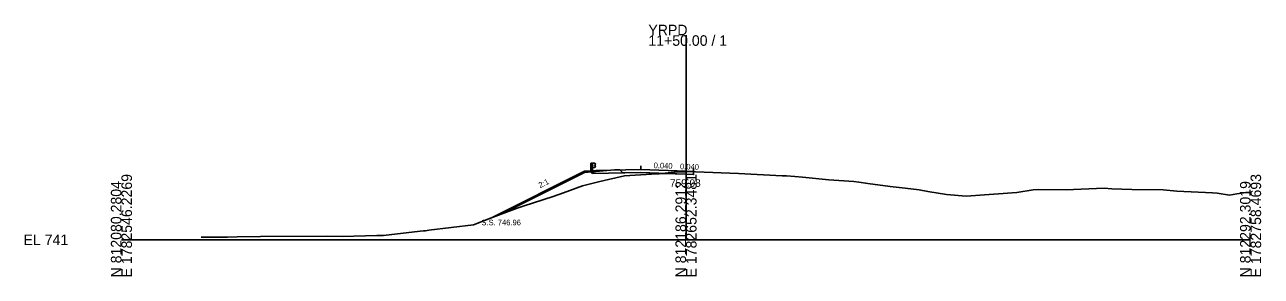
# Model space of a CAD drawing. Extents: x -26 to 1403, y -10 to 9544.
# Drawn here: x -25.7 to 302.8, y 1490.3 to 1557.2 of the extents above; entities that cross this region are included whole.
import ezdxf

# ---------------------------------------------------------------- set-up
doc = ezdxf.new("R2010")
doc.units = 0
for name, color, linetype in [('Exist Cross Section Cell', 7, 'Continuous'), ('Exist XS Center Line Elevation Label', 7, 'Continuous'), ('Exist XS Ground Line', 7, 'Continuous'), ('Prop XS Dump Level', 7, 'Continuous'), ('Prop XS Earthwork Shape', 7, 'Continuous'), ('Prop XS EOT Tick Mark', 7, 'Continuous'), ('Prop XS Finish Grade', 7, 'Continuous'), ('Prop XS Finish Grade Earthwork', 7, 'Continuous'), ('Prop XS Finish Grade Paved Shoulder', 7, 'Continuous'), ('Prop XS Finish Grade Pavement', 7, 'Continuous'), ('Prop XS Guardrail', 7, 'Continuous'), ('Prop XS Pvmt Edge Slope', 7, 'Continuous'), ('Prop XS SE Text', 7, 'Continuous'), ('Prop XS Side Slope Text', 7, 'Continuous'), ('Prop XS SS Elevation Text', 7, 'Continuous'), ('Prop XS Subgrade Earthwork', 7, 'Continuous')]:
    doc.layers.add(name, color=color, linetype=linetype)

msp = doc.modelspace()

# ---------------------------------------------------------------- linework, layer by layer
at = {"layer": 'Exist Cross Section Cell'}
for p, q in [((150, 1500), (150, 1554.35)), ((0, 1500), (150, 1500)), ((150, 1500), (300, 1500))]:
    msp.add_line(p, q, dxfattribs=at)
at = {"layer": 'Exist XS Ground Line'}
for p, q in [((142.9, 1517.49), (147.62, 1518.04)), ((147.62, 1518.04), (149.08, 1518.07)), ((149.08, 1518.07), (150, 1518.08)), ((150, 1518.08), (152.12, 1518.12)), ((152.12, 1518.12), (152.55, 1518.1)), ((152.55, 1518.1), (163.95, 1517.65)), ((122.46, 1514.34), (127.13, 1515.48)), ((127.13, 1515.48), (133.67, 1516.98)), ((133.67, 1516.98), (140.8, 1517.41)), ((140.8, 1517.41), (142.9, 1517.49)), ((163.95, 1517.65), (175.58, 1517.03)), ((175.58, 1517.03), (176.7, 1516.96)), ((176.7, 1516.96), (178.88, 1516.83)), ((178.88, 1516.83), (180.91, 1516.61)), ((180.91, 1516.61), (187.99, 1515.97)), ((187.99, 1515.97), (194.56, 1515.47)), ((194.56, 1515.47), (195.89, 1515.31)), ((195.89, 1515.31), (198.3, 1514.98)), ((198.3, 1514.98), (204.21, 1514.13)), ((109.48, 1509.8), (114.7, 1511.47)), ((114.7, 1511.47), (117.46, 1512.51)), ((117.46, 1512.51), (122.46, 1514.34)), ((204.21, 1514.13), (208.2, 1513.7)), ((208.2, 1513.7), (211.95, 1513.31)), ((211.95, 1513.31), (214.25, 1512.87)), ((214.25, 1512.87), (219.18, 1512.04)), ((219.18, 1512.04), (224.47, 1511.63)), ((224.47, 1511.63), (237.91, 1512.57)), ((237.91, 1512.57), (242.24, 1513.32)), ((242.24, 1513.32), (243.57, 1513.35)), ((243.57, 1513.35), (250.98, 1513.28)), ((250.98, 1513.28), (252.95, 1513.35)), ((252.95, 1513.35), (261.09, 1513.73)), ((261.09, 1513.73), (263.13, 1513.55)), ((263.13, 1513.55), (268.43, 1513.36)), ((268.43, 1513.36), (276.79, 1513.3)), ((276.79, 1513.3), (280.43, 1512.92)), ((280.43, 1512.92), (289.85, 1512.52)), ((289.85, 1512.52), (291.1, 1512.35)), ((291.1, 1512.35), (294.41, 1511.88)), ((294.41, 1511.88), (296.38, 1512.2)), ((296.38, 1512.2), (298.72, 1512.55)), ((298.72, 1512.55), (300, 1512.59)), ((98.04, 1505.79), (105.1, 1508.43)), ((105.1, 1508.43), (106.98, 1508.99)), ((106.98, 1508.99), (109.48, 1509.8)), ((93.58, 1503.96), (98.04, 1505.79)), ((69.59, 1501.18), (79.36, 1502.27)), ((79.36, 1502.27), (80.24, 1502.34)), ((80.24, 1502.34), (80.77, 1502.4)), ((80.77, 1502.4), (81.68, 1502.52)), ((81.68, 1502.52), (93.58, 1503.96)), ((21.2, 1500.67), (28.15, 1500.69)), ((28.15, 1500.69), (30.71, 1500.75)), ((30.71, 1500.75), (36.99, 1500.85)), ((36.99, 1500.85), (54.44, 1500.95)), ((54.44, 1500.95), (58.77, 1500.87)), ((58.77, 1500.87), (67.89, 1501.13)), ((67.89, 1501.13), (69.59, 1501.18))]:
    msp.add_line(p, q, dxfattribs=at)
at = {"layer": 'Prop XS Dump Level'}
for p, q in [((138, 1518.69), (150, 1518.21)), ((150, 1518.21), (152, 1518.13))]:
    msp.add_line(p, q, dxfattribs=at)
at = {"layer": 'Prop XS Earthwork Shape'}
for points in [[(123, 1517.91), (100.87, 1506.85), (105.1, 1508.43), (106.98, 1508.99), (109.48, 1509.8), (114.7, 1511.47), (117.46, 1512.51), (122.46, 1514.34), (127.13, 1515.48), (133.67, 1516.98), (140.8, 1517.41), (142.9, 1517.49), (144.27, 1517.65), (137.99, 1517.9), (133.19, 1517.8), (132.42, 1518.58), (131, 1518.55)], [(149.97, 1517.42), (152, 1517.34), (152, 1518.12), (150, 1518.08), (149.08, 1518.07), (147.62, 1518.04), (144.27, 1517.65)]]:
    msp.add_lwpolyline(points, close=True, dxfattribs=at)
at = {"layer": 'Prop XS EOT Tick Mark'}
for p, q in [((138, 1518.69), (138, 1519.69)), ((152, 1518.13), (152, 1519.13))]:
    msp.add_line(p, q, dxfattribs=at)
at = {"layer": 'Prop XS Finish Grade'}
msp.add_line((124.5, 1518.33), (126, 1518.45), dxfattribs=at)
at = {"layer": 'Prop XS Finish Grade Earthwork'}
for q in [(98.5, 1505.96), (124.5, 1518.33)]:
    msp.add_line((123, 1518.21), q, dxfattribs=at)
at = {"layer": 'Prop XS Finish Grade Paved Shoulder'}
msp.add_line((138, 1518.69), (126, 1518.45), dxfattribs=at)
at = {"layer": 'Prop XS Finish Grade Pavement'}
for p, q in [((138, 1518.69), (150, 1518.21)), ((150, 1518.21), (152, 1518.13))]:
    msp.add_line(p, q, dxfattribs=at)
at = {"layer": 'Prop XS Guardrail'}
for p, q in [((124.68, 1520.36), (125.18, 1520.36)), ((124.68, 1517.86), (124.68, 1520.36)), ((125.18, 1520.36), (125.68, 1520.36)), ((125.18, 1520.36), (125.18, 1517.86)), ((125.68, 1519.23), (125.18, 1519.23)), ((125.68, 1520.36), (125.97, 1520.16)), ((125.97, 1520.04), (125.68, 1519.84)), ((125.68, 1519.84), (125.68, 1519.75)), ((125.68, 1519.75), (125.97, 1519.55)), ((125.97, 1519.43), (125.68, 1519.23)), ((125.97, 1520.16), (126, 1520.1)), ((126, 1520.1), (125.97, 1520.04)), ((125.97, 1519.55), (126, 1519.49)), ((126, 1519.49), (125.97, 1519.43))]:
    msp.add_line(p, q, dxfattribs=at)
at = {"layer": 'Prop XS Pvmt Edge Slope'}
msp.add_line((126, 1518.45), (125.19, 1517.64), dxfattribs=at)
at = {"layer": 'Prop XS Subgrade Earthwork'}
for p, q in [((125.19, 1517.64), (124.5, 1518.33)), ((137.99, 1517.9), (125.19, 1517.64)), ((137.99, 1517.9), (149.97, 1517.42)), ((152, 1517.34), (152, 1518.12)), ((149.97, 1517.42), (152, 1517.34))]:
    msp.add_line(p, q, dxfattribs=at)

# ---------------------------------------------------------------- texts
at = {"layer": 'Exist Cross Section Cell'}
for s, p in [('YRPD', (140, 1554.35)), ('11+50.00 / 1', (140, 1551.55)), ('EL 741', (-26, 1498.6))]:
    msp.add_text(s, height=2.8, dxfattribs=at).set_placement(p)
for s, p in [('N 812080.2804', (0, 1490)), ('E 1782546.2269', (2.8, 1490)), ('N 812186.2912', (150, 1490)), ('E 1782652.3481', (152.8, 1490)), ('N 812292.3019', (300, 1490)), ('E 1782758.4693', (302.8, 1490))]:
    msp.add_text(s, height=2.8, rotation=90, dxfattribs=at).set_placement(p)
at = {"layer": 'Exist XS Center Line Elevation Label'}
msp.add_text('759.08', height=2, dxfattribs=at).set_placement((145.73, 1514.08))
at = {"layer": 'Prop XS Dump Level'}
msp.add_text('Case4', height=0.04, dxfattribs=at).set_placement((126, 1518.11))
at = {"layer": 'Prop XS SE Text'}
for p in [(141.38, 1519.05), (148.38, 1518.77)]:
    msp.add_text('0.040', height=1.5, rotation=357.7094, dxfattribs=at).set_placement(p)
at = {"layer": 'Prop XS Side Slope Text'}
msp.add_text('2:1', height=1.5, rotation=26.5651, dxfattribs=at).set_placement((111.27, 1513.72))
at = {"layer": 'Prop XS SS Elevation Text'}
msp.add_text('S.S. 746.96', height=1.5, dxfattribs=at).set_placement((95.65, 1503.85))

doc.saveas('drawing.dxf')
